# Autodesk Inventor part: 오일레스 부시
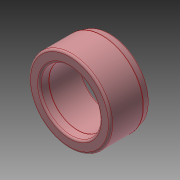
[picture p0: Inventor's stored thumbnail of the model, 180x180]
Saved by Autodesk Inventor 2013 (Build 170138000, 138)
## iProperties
Created: 2023-11
Part Number: 오일레스 부시
Material: 강철, 합금
Document SubType Name: Modeling
Designer: mdu-01
Density: 1 g/cm^3
Author: mdu-01
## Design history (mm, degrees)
sketch "스케치1"
  geometry: L1 (7.772, 0)-(9.5, 0); L2 (10, -0.5)-(10, -7.934); L3 (9.08, -10)-(7.5, -10); L4 (7, -9.5)-(7, -2.044); L5 (0, 0)-(0, -10); L6 (9.983, -8.064)-(9.563, -9.629); L7 (7.008, -1.957)-(7.28, -0.413); A1 r 0.5 centre (9.5, -0.5) between (10, -0.5) and (9.5, 0); A2 r 0.5 centre (7.5, -9.5) between (7, -9.5) and (7.5, -10); A3 r 0.5 centre (9.08, -9.5) between (9.08, -10) and (9.563, -9.629); A4 r 0.5 centre (7.772, -0.5) between (7.772, 0) and (7.28, -0.413); A5 r 0.5 centre (7.5, -2.044) between (7.008, -1.957) and (7, -2.044); A6 r 0.5 centre (9.5, -7.934) between (9.983, -8.064) and (10, -7.934); 4 further points
  constraints: 14 end point, 12 point on circle, 12 tangent, 10 point on line, 6 centre point, 4 equal radius, 3 parallel, 1 horizontal, 1 perpendicular
  dimensions: "d0" = 10 distance of L5.start L5.end; "d1" = 14 diameter of L4 L5; "d2" = 20 diameter of L2 L5; "d3" = 0.5 radius of A1; "d4" = 2 distance of point (10, -8) point (10, -10); "d5" = 15 deg angle of L2 L6; "d6" = 2 distance of point (7, -2) point (7, 0); "d7" = 10 deg angle of L4 L7; "d8" = 0.5 radius of A3
revolve "회전1" sketch "스케치1" stored, may be unused: angle "d9" = 90 deg
node "솔리드1"
